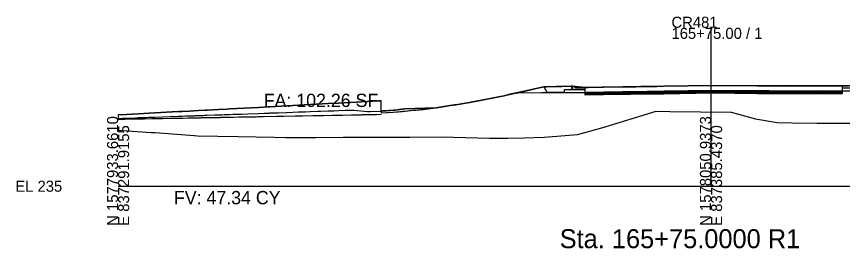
# Model space of a CAD drawing. Extents: x -26 to 303, y -16 to 6048.
# Drawn here: x -25.7 to 183.3, y 5484.3 to 5542.8 of the extents above; entities that cross this region are included whole.
import ezdxf

# ---------------------------------------------------------------- set-up
doc = ezdxf.new("R2010")
doc.units = 0
for name, color, linetype in [('ASPHALT_19MM1', 7, 'Continuous'), ('ASPHALT_9_5MM1', 7, 'Continuous'), ('CONST_LV3', 7, 'Continuous'), ('Default', 7, 'Continuous'), ('Draft_XS_Grid', 7, 'Continuous'), ('Draft_XS_Text', 7, 'Continuous'), ('DTM_P_FINISHED_GRADE', 7, 'Continuous'), ('DTM_P_FINISHED_GRADE2', 7, 'Continuous'), ('DTM_X_GROUND', 7, 'Continuous'), ('TRANS_PAVED_SHOULDERS', 7, 'Continuous'), ('X_PROFILES_1', 7, 'Continuous'), ('XS_CELL', 7, 'Continuous'), ('XS_M_SHAPES_EARTHWORK', 7, 'Continuous'), ('XS_P_ASPHALT', 7, 'Continuous'), ('XS_P_CONCRETE', 7, 'Continuous'), ('XS_P_GROUND', 7, 'Continuous'), ('XS_P_SHOULDER', 7, 'Continuous'), ('XS_P_SUBGRADE_GRANULAR', 7, 'Continuous'), ('XS_P_SUBGRADE_GRANULAR_B', 7, 'Continuous'), ('XS_SHEET_EW_TX_AREA', 7, 'Continuous'), ('XS_SHEET_EW_TX_VOLUME', 7, 'Continuous')]:
    doc.layers.add(name, color=color, linetype=linetype)

msp = doc.modelspace()

# ---------------------------------------------------------------- linework, layer by layer
at = {"layer": 'ASPHALT_19MM1'}
msp.add_lwpolyline([(118.12, 5523.35), (118.12, 5523.08), (127.61, 5523.2), (129.55, 5523.24), (138.17, 5523.35), (150, 5523.55), (161.79, 5523.45), (164.74, 5523.45), (167.03, 5523.43), (178.55, 5523.45), (180.57, 5523.44), (183.26, 5523.45), (183.26, 5523.72), (180.57, 5523.71), (178.55, 5523.72), (167.03, 5523.7), (164.74, 5523.72), (161.79, 5523.72), (150, 5523.82), (138.17, 5523.62), (129.55, 5523.51), (127.61, 5523.48), (118.12, 5523.35)], dxfattribs=at)
at = {"layer": 'ASPHALT_9_5MM1'}
msp.add_lwpolyline([(118.12, 5523.68), (118.12, 5523.56), (127.61, 5523.68), (129.55, 5523.72), (138.17, 5523.83), (150, 5524.03), (161.79, 5523.93), (164.74, 5523.93), (167.03, 5523.91), (178.55, 5523.93), (180.57, 5523.92), (183.26, 5523.93), (183.26, 5524.06), (180.57, 5524.04), (178.55, 5524.05), (167.03, 5524.04), (164.74, 5524.05), (161.79, 5524.05), (150, 5524.15), (138.17, 5523.96), (129.55, 5523.84), (127.61, 5523.81), (118.12, 5523.68)], dxfattribs=at)
at = {"layer": 'CONST_LV3'}
for points in [[(66.56, 5518.56), (68, 5518.63), (69.49, 5518.72), (70.4, 5518.78), (71.38, 5518.86), (71.92, 5518.9), (72.51, 5518.95), (73.97, 5519.08), (75.68, 5519.25), (77.14, 5519.41), (79.02, 5519.64), (80.47, 5519.83), (82.6, 5520.13), (84.03, 5520.34), (86.47, 5520.73), (87.85, 5520.96), (90.73, 5521.48), (92.01, 5521.71), (95.49, 5522.4), (96.57, 5522.62), (100.89, 5523.54), (101.62, 5523.7), (107.14, 5524.98), (107.22, 5525), (107.72, 5525.12), (110.94, 5525.19), (114.56, 5525.26), (114.68, 5525.27), (114.79, 5525.27)], [(66.56, 5518.56), (68.2, 5518.65), (69.48, 5518.73), (69.49, 5518.73), (69.49, 5518.73), (69.51, 5518.73), (69.52, 5518.73), (69.53, 5518.73), (69.54, 5518.73), (69.59, 5518.73), (69.62, 5518.73), (70.4, 5518.8), (71.35, 5518.87), (71.37, 5518.87), (71.38, 5518.87), (71.92, 5518.91), (72.51, 5518.96), (72.51, 5518.96), (72.51, 5518.96), (72.54, 5518.96), (72.57, 5518.97), (72.6, 5518.97), (72.63, 5518.97), (73.23, 5519.02), (73.83, 5519.08), (74.72, 5519.17), (75.67, 5519.27), (75.67, 5519.27), (75.68, 5519.27), (75.72, 5519.27), (75.77, 5519.28), (75.81, 5519.28), (75.86, 5519.29), (76.48, 5519.36), (77.19, 5519.44), (77.99, 5519.53), (79.01, 5519.66), (79.01, 5519.66), (79.02, 5519.66), (79.03, 5519.67), (79.03, 5519.67), (79.08, 5519.67), (79.15, 5519.68), (79.21, 5519.69), (79.28, 5519.7), (79.88, 5519.77), (80.73, 5519.89), (81.46, 5519.99), (82.6, 5520.16), (82.6, 5520.16), (82.61, 5520.16), (82.67, 5520.17), (82.77, 5520.18), (82.84, 5520.19), (82.95, 5520.21), (83.52, 5520.29), (84.51, 5520.45), (85.18, 5520.55), (86.47, 5520.77), (86.48, 5520.77), (86.5, 5520.77), (86.56, 5520.78), (86.7, 5520.8), (86.78, 5520.82), (86.93, 5520.84), (87.45, 5520.93), (88.64, 5521.14), (89.22, 5521.24), (90.73, 5521.52), (90.81, 5521.53), (91.03, 5521.57), (91.1, 5521.59), (91.33, 5521.63), (91.77, 5521.71), (93.21, 5521.99), (93.67, 5522.08), (95.45, 5522.44), (95.45, 5522.44), (95.49, 5522.45), (95.49, 5522.45), (95.52, 5522.46), (95.59, 5522.47), (95.87, 5522.52), (95.94, 5522.54), (96.25, 5522.6), (96.59, 5522.67), (98.37, 5523.05), (98.69, 5523.11), (100.89, 5523.6), (100.89, 5523.6), (100.93, 5523.61), (100.98, 5523.62), (101.38, 5523.71), (101.43, 5523.72), (101.88, 5523.82), (102.06, 5523.86), (104.28, 5524.37), (104.41, 5524.4), (107.14, 5525.05), (107.15, 5525.05), (107.46, 5525.12), (107.76, 5525.12), (107.79, 5525.12), (108.35, 5525.13), (108.43, 5525.14), (110.15, 5525.17), (111.23, 5525.19), (112.28, 5525.21), (114.47, 5525.26), (114.48, 5525.26), (114.55, 5525.27), (114.56, 5525.27), (114.63, 5525.27), (114.65, 5525.27), (114.8, 5525.27)], [(107.46, 5525.12), (107.79, 5525.12), (108.43, 5525.14), (111.23, 5525.19), (114.47, 5525.26), (114.55, 5525.27), (114.63, 5525.27), (114.8, 5525.27)], [(114.8, 5525.27), (114.8, 5524.44), (115.41, 5524.44), (116.26, 5524.44), (118.17, 5524.45), (118.17, 5524.95), (116.26, 5524.94), (115.73, 5524.94), (115.73, 5525.02), (115.41, 5525.11), (114.8, 5525.27)], [(118.12, 5524.96), (118.12, 5523.68), (127.61, 5523.81), (129.55, 5523.84), (138.17, 5523.96), (150, 5524.15), (161.79, 5524.05), (164.74, 5524.05), (167.03, 5524.04), (178.55, 5524.05), (180.57, 5524.04), (183.26, 5524.06), (183.26, 5525.33), (180.57, 5525.31), (178.55, 5525.32), (167.03, 5525.31), (164.74, 5525.32), (161.79, 5525.32), (150, 5525.43), (138.17, 5525.23), (129.55, 5525.11), (127.61, 5525.08), (118.12, 5524.96)], [(183.22, 5525.33), (183.22, 5524.83), (183.64, 5524.83), (186.77, 5524.85), (186.77, 5525.68), (185.8, 5525.43), (185.79, 5525.34), (183.64, 5525.33), (183.22, 5525.33)], [(112.9, 5523.65), (112.9, 5524.42), (114.56, 5524.43), (114.79, 5524.44)]]:
    msp.add_lwpolyline(points, dxfattribs=at)
at = {"layer": 'Default'}
msp.add_lwpolyline([(118.17, 5524.95), (118.91, 5524.96), (121.04, 5524.99), (126.79, 5525.07), (129.55, 5525.11), (129.69, 5525.11), (131, 5525.13), (132.25, 5525.15), (135.58, 5525.19), (138.17, 5525.23), (150, 5525.43), (161.85, 5525.32), (164.64, 5525.32), (164.71, 5525.32), (164.73, 5525.32), (164.74, 5525.32), (165.15, 5525.32), (165.21, 5525.32), (168.55, 5525.3), (178.8, 5525.32), (182.04, 5525.31), (182.08, 5525.31), (182.1, 5525.31), (182.1, 5525.31), (182.38, 5525.31), (183.22, 5525.33)], dxfattribs=at)
msp.add_lwpolyline([(118.17, 5523.08), (118.17, 5524.95), (118.91, 5524.96), (121.04, 5524.99), (126.79, 5525.07), (129.55, 5525.11), (129.69, 5525.11), (131, 5525.13), (132.25, 5525.15), (135.58, 5525.19), (138.17, 5525.23), (150, 5525.43), (161.85, 5525.32), (164.64, 5525.32), (164.71, 5525.32), (164.73, 5525.32), (164.74, 5525.32), (165.15, 5525.32), (165.21, 5525.32), (168.55, 5525.3), (178.8, 5525.32), (182.04, 5525.31), (182.08, 5525.31), (182.1, 5525.31), (182.1, 5525.31), (182.38, 5525.31), (183.22, 5525.33), (183.22, 5523.45), (180.57, 5523.44), (178.55, 5523.45), (167.03, 5523.43), (164.74, 5523.45), (161.79, 5523.45), (150, 5523.55), (138.17, 5523.35), (129.55, 5523.24), (127.61, 5523.2)], close=True, dxfattribs=at)
at = {"layer": 'DTM_P_FINISHED_GRADE'}
msp.add_lwpolyline([(118.12, 5524.96), (127.61, 5525.08), (129.55, 5525.11), (138.17, 5525.23), (150, 5525.43), (161.79, 5525.32), (164.74, 5525.32), (167.03, 5525.31), (178.55, 5525.32), (180.57, 5525.31), (183.26, 5525.33)], dxfattribs=at)
at = {"layer": 'DTM_P_FINISHED_GRADE2'}
msp.add_lwpolyline([(66.56, 5518.56), (68, 5518.63), (69.49, 5518.72), (70.4, 5518.78), (70.94, 5518.82), (71.92, 5518.9), (73.37, 5519.03), (73.97, 5519.08), (75.43, 5519.24), (77.14, 5519.41), (78.6, 5519.6), (80.47, 5519.83), (81.93, 5520.04), (84.03, 5520.34), (85.47, 5520.58), (87.85, 5520.96), (89.24, 5521.22), (92.01, 5521.71), (93.29, 5521.97), (94.58, 5522.25), (97.65, 5522.85), (98.77, 5523.12), (102.35, 5523.88), (103.13, 5524.07), (107.3, 5525.02), (107.72, 5525.12), (110.94, 5525.19), (114.56, 5525.26), (114.68, 5525.27), (114.79, 5525.27), (115.59, 5525.05), (115.71, 5525.02), (115.71, 5525.01), (115.71, 5524.94), (117.31, 5524.95), (118.12, 5524.96), (127.61, 5525.08), (129.55, 5525.11), (138.17, 5525.23), (150, 5525.43), (161.79, 5525.32), (164.74, 5525.32), (167.03, 5525.31), (178.55, 5525.32), (180.57, 5525.31), (183.26, 5525.33)], dxfattribs=at)
at = {"layer": 'DTM_X_GROUND'}
for points in [[(0, 5517.13), (1.15, 5517.17), (2.13, 5517.2), (4.44, 5517.28), (5.15, 5517.31), (6.05, 5517.34), (7.15, 5517.38), (7.81, 5517.4), (9.32, 5517.46), (13.15, 5517.59), (15.27, 5517.67), (15.43, 5517.67), (15.93, 5517.69), (16.15, 5517.7), (17.18, 5517.73), (17.24, 5517.74), (17.46, 5517.74), (17.99, 5517.76), (19.34, 5517.81), (19.6, 5517.82), (20.31, 5517.85), (21.53, 5517.89), (21.84, 5517.9), (22.41, 5517.92), (22.56, 5517.92), (24.44, 5517.99), (25.39, 5518.03), (26.26, 5518.06), (26.86, 5518.08), (27.21, 5518.09), (27.99, 5518.12), (28.18, 5518.12), (29.01, 5518.15), (31.19, 5518.23), (32.8, 5518.29), (35.51, 5518.39), (37, 5518.44), (37.94, 5518.47), (38.2, 5518.48), (38.37, 5518.49), (39.09, 5518.51), (40.62, 5518.57), (42.49, 5518.63), (42.65, 5518.64), (45.63, 5518.74), (47.33, 5518.8), (48.56, 5518.85), (50.62, 5518.92), (51.17, 5518.94), (53.16, 5519.01), (54.44, 5519.06), (54.61, 5519.06), (55.75, 5519.1), (57.41, 5519.16), (58.75, 5519.21), (59.61, 5519.24), (63.13, 5518.84), (63.81, 5518.87), (66.25, 5518.96), (66.78, 5518.99), (67, 5519), (67.07, 5519.01), (67.45, 5519.03), (67.68, 5519.04), (67.75, 5519.04), (68.5, 5519.09), (68.93, 5519.13), (69.78, 5519.21), (70.11, 5519.24), (71.21, 5519.38), (71.28, 5519.38), (72.43, 5519.55), (80.47, 5519.83), (81.93, 5520.04), (84.03, 5520.34), (85.13, 5520.52), (85.47, 5520.58), (87.85, 5520.96), (89, 5521.17), (89.24, 5521.22), (92.01, 5521.71), (93.29, 5521.97), (94.18, 5522.17), (94.58, 5522.25), (97.65, 5522.85), (98.77, 5523.12), (102.35, 5523.88), (102.45, 5523.9), (103.13, 5524.07), (103.13, 5524.07), (107.3, 5525.02), (107.72, 5525.12), (110.94, 5525.19), (114.56, 5525.26), (114.68, 5525.27), (114.79, 5525.27), (114.95, 5525.25), (118.12, 5524.96), (127.61, 5525.08), (129.55, 5525.11), (138.17, 5525.23), (150, 5525.43), (161.79, 5525.32), (164.74, 5525.32), (167.03, 5525.31), (178.55, 5525.32), (180.57, 5525.31), (183.26, 5525.33), (184.75, 5525.38)], [(0, 5514.15), (8.39, 5513.55), (9.36, 5513.53), (19.24, 5512.79), (19.31, 5512.79), (20.08, 5512.73), (30.35, 5512.53), (39.51, 5512.35), (42.48, 5512.29), (50.02, 5512.34), (56.93, 5512.37), (65.45, 5512.36), (73.85, 5512.39), (81.83, 5512.43), (93.98, 5512.09), (98.6, 5512.09), (102.8, 5512.24), (107.81, 5512.42), (115.22, 5512.99), (116.25, 5513.02), (122.34, 5514.73), (136.13, 5518.91), (139.56, 5518.89), (155.1, 5518.72), (161.24, 5517), (166.75, 5516.08), (170.55, 5516.03), (176.89, 5515.95), (180.55, 5515.96), (186.64, 5515.89)]]:
    msp.add_lwpolyline(points, dxfattribs=at)
at = {"layer": 'TRANS_PAVED_SHOULDERS'}
msp.add_lwpolyline([(118.12, 5523.56), (118.12, 5523.35), (127.61, 5523.48), (129.55, 5523.51), (138.17, 5523.62), (150, 5523.82), (161.79, 5523.72), (164.74, 5523.72), (167.03, 5523.7), (178.55, 5523.72), (180.57, 5523.71), (183.26, 5523.72), (183.26, 5523.93), (180.57, 5523.92), (178.55, 5523.93), (167.03, 5523.91), (164.74, 5523.93), (161.79, 5523.93), (150, 5524.03), (138.17, 5523.83), (129.55, 5523.72), (127.61, 5523.68), (118.12, 5523.56)], dxfattribs=at)
at = {"layer": 'XS_CELL'}
for p, q in [((150, 5500), (150, 5540)), ((0, 5500), (150, 5500)), ((150, 5500), (300, 5500))]:
    msp.add_line(p, q, dxfattribs=at)
at = {"layer": 'XS_M_SHAPES_EARTHWORK'}
for points in [[(126.82, 5525.07), (118.12, 5524.96), (114.95, 5525.25), (114.79, 5525.27), (114.68, 5525.27), (114.56, 5525.26), (110.94, 5525.19), (107.72, 5525.12), (107.3, 5525.02), (103.13, 5524.07), (102.45, 5523.9), (102.35, 5523.88), (98.77, 5523.12), (97.65, 5522.85), (94.58, 5522.25), (94.18, 5522.17), (93.29, 5521.97), (92.01, 5521.71), (95.49, 5522.4), (96.57, 5522.62), (100.89, 5523.54), (101.18, 5523.61), (107.14, 5523.63), (108.45, 5523.63), (112.9, 5523.65), (114.56, 5523.66), (114.79, 5523.66), (118.12, 5523.68), (118.12, 5523.56), (118.12, 5523.35), (118.12, 5523.08), (118.17, 5523.08), (118.17, 5524.95), (118.91, 5524.96), (121.04, 5524.99), (126.79, 5525.07)], [(132.25, 5525.15), (130.81, 5525.13), (131, 5525.13)], [(136.32, 5525.2), (132.25, 5525.15), (135.58, 5525.19)], [(179.9, 5525.32), (178.55, 5525.32), (167.49, 5525.31), (168.55, 5525.3), (178.8, 5525.32)], [(0, 5518.03), (0, 5517.13), (1.15, 5517.17), (2.13, 5517.2), (4.44, 5517.28), (5.15, 5517.31), (6.05, 5517.34), (7.15, 5517.38), (7.81, 5517.4), (9.32, 5517.46), (13.15, 5517.59), (15.27, 5517.67), (15.43, 5517.67), (15.93, 5517.69), (16.15, 5517.7), (17.18, 5517.73), (17.24, 5517.74), (17.46, 5517.74), (17.99, 5517.76), (19.34, 5517.81), (19.6, 5517.82), (20.31, 5517.85), (21.53, 5517.89), (21.84, 5517.9), (22.41, 5517.92), (22.56, 5517.92), (24.44, 5517.99), (25.39, 5518.03), (26.26, 5518.06), (26.86, 5518.08), (27.21, 5518.09), (27.99, 5518.12), (28.18, 5518.12), (29.01, 5518.15), (31.19, 5518.23), (32.8, 5518.29), (35.51, 5518.39), (37, 5518.44), (37.94, 5518.47), (38.2, 5518.48), (38.37, 5518.49), (39.09, 5518.51), (40.62, 5518.57), (42.49, 5518.63), (42.65, 5518.64), (45.63, 5518.74), (47.33, 5518.8), (48.56, 5518.85), (50.62, 5518.92), (51.17, 5518.94), (53.16, 5519.01), (54.44, 5519.06), (54.61, 5519.06), (55.75, 5519.1), (57.41, 5519.16), (58.75, 5519.21), (59.61, 5519.24), (63.13, 5518.84), (63.81, 5518.87), (66.25, 5518.96), (66.56, 5518.98), (66.56, 5521.58), (66.4, 5521.58), (65.88, 5521.55), (60.31, 5521.25), (58.75, 5521.16), (55.75, 5521), (53.16, 5520.86), (48.56, 5520.61), (45.63, 5520.45), (38.37, 5520.06), (37.94, 5520.04), (35.51, 5519.91), (28.18, 5519.52), (27.63, 5519.49), (25.39, 5519.37), (22.56, 5519.22), (22.1, 5519.2), (20.31, 5519.1), (17.99, 5518.98), (16.21, 5518.88), (15.49, 5518.84), (15.27, 5518.83), (7.81, 5518.44), (5.15, 5518.3), (2.13, 5518.14)], [(86.47, 5520.73), (87.85, 5520.96), (85.47, 5520.58), (85.13, 5520.52), (84.03, 5520.34)], [(90.73, 5521.48), (92.01, 5521.71), (89.24, 5521.22), (89, 5521.17), (87.85, 5520.96)], [(68, 5518.63), (69.49, 5518.72), (70.4, 5518.78), (71.38, 5518.86), (71.92, 5518.9), (72.51, 5518.95), (73.97, 5519.08), (75.68, 5519.25), (77.14, 5519.41), (79.02, 5519.64), (80.47, 5519.83), (72.43, 5519.55), (71.28, 5519.38), (71.21, 5519.38), (70.11, 5519.24), (69.78, 5519.21), (68.93, 5519.13), (68.5, 5519.09), (67.75, 5519.04), (67.68, 5519.04), (67.45, 5519.03), (67.07, 5519.01), (67, 5519), (66.78, 5518.99), (66.56, 5518.98), (66.56, 5518.56)], [(82.6, 5520.13), (84.03, 5520.34), (81.93, 5520.04), (80.47, 5519.83)]]:
    msp.add_lwpolyline(points, close=True, dxfattribs=at)
msp.add_lwpolyline([(184.75, 5525.38), (183.26, 5525.33), (180.68, 5525.31), (182.04, 5525.31), (182.08, 5525.31), (182.1, 5525.31), (182.1, 5525.31), (182.38, 5525.31), (183.22, 5525.33), (183.22, 5523.45), (183.26, 5523.45), (183.26, 5523.72), (183.26, 5523.93), (183.26, 5524.06), (186.8, 5524.08)], dxfattribs=at)
at = {"layer": 'XS_P_ASPHALT'}
msp.add_lwpolyline([(118.12, 5524.96), (127.61, 5525.08), (129.55, 5525.11), (138.17, 5525.23), (150, 5525.43), (161.79, 5525.32), (164.74, 5525.32), (167.03, 5525.31), (178.55, 5525.32), (180.57, 5525.31), (183.26, 5525.33)], dxfattribs=at)
at = {"layer": 'XS_P_CONCRETE'}
msp.add_lwpolyline([(118.12, 5524.96), (118.12, 5524.46), (114.79, 5524.44), (114.79, 5525.27), (115.71, 5525.02), (115.71, 5524.94), (118.12, 5524.96)], dxfattribs=at)
at = {"layer": 'XS_P_GROUND'}
for points in [[(66.56, 5518.56), (68, 5518.63), (69.49, 5518.72), (70.4, 5518.78), (71.38, 5518.86), (71.92, 5518.9), (72.51, 5518.95), (73.97, 5519.08), (75.68, 5519.25), (77.14, 5519.41), (79.02, 5519.64), (80.47, 5519.83), (82.6, 5520.13), (84.03, 5520.34), (86.47, 5520.73), (87.85, 5520.96), (90.73, 5521.48), (92.01, 5521.71), (95.49, 5522.4), (96.57, 5522.62), (100.89, 5523.54), (101.62, 5523.7), (107.14, 5524.98), (107.22, 5525), (107.72, 5525.12)], [(66.56, 5518.56), (68.2, 5518.65), (69.48, 5518.73), (69.49, 5518.73), (69.49, 5518.73), (69.51, 5518.73), (69.52, 5518.73), (69.53, 5518.73), (69.54, 5518.73), (69.59, 5518.73), (69.62, 5518.73), (70.4, 5518.8), (71.35, 5518.87), (71.37, 5518.87), (71.38, 5518.87), (71.92, 5518.91), (72.51, 5518.96), (72.51, 5518.96), (72.51, 5518.96), (72.54, 5518.96), (72.57, 5518.97), (72.6, 5518.97), (72.63, 5518.97), (73.23, 5519.02), (73.83, 5519.08), (74.72, 5519.17), (75.67, 5519.27), (75.67, 5519.27), (75.68, 5519.27), (75.72, 5519.27), (75.77, 5519.28), (75.81, 5519.28), (75.86, 5519.29), (76.48, 5519.36), (77.19, 5519.44), (77.99, 5519.53), (79.01, 5519.66), (79.01, 5519.66), (79.02, 5519.66), (79.03, 5519.67), (79.03, 5519.67), (79.08, 5519.67), (79.15, 5519.68), (79.21, 5519.69), (79.28, 5519.7), (79.88, 5519.77), (80.73, 5519.89), (81.46, 5519.99), (82.6, 5520.16), (82.6, 5520.16), (82.61, 5520.16), (82.67, 5520.17), (82.77, 5520.18), (82.84, 5520.19), (82.95, 5520.21), (83.52, 5520.29), (84.51, 5520.45), (85.18, 5520.55), (86.47, 5520.77), (86.48, 5520.77), (86.5, 5520.77), (86.56, 5520.78), (86.7, 5520.8), (86.78, 5520.82), (86.93, 5520.84), (87.45, 5520.93), (88.64, 5521.14), (89.22, 5521.24), (90.73, 5521.52), (90.81, 5521.53), (91.03, 5521.57), (91.1, 5521.59), (91.33, 5521.63), (91.77, 5521.71), (93.21, 5521.99), (93.67, 5522.08), (95.45, 5522.44), (95.45, 5522.44), (95.49, 5522.45), (95.49, 5522.45), (95.52, 5522.46), (95.59, 5522.47), (95.87, 5522.52), (95.94, 5522.54), (96.25, 5522.6), (96.59, 5522.67), (98.37, 5523.05), (98.69, 5523.11), (100.89, 5523.6), (100.89, 5523.6), (100.93, 5523.61), (100.98, 5523.62), (101.38, 5523.71), (101.43, 5523.72), (101.88, 5523.82), (102.06, 5523.86), (104.28, 5524.37), (104.41, 5524.4), (107.14, 5525.05), (107.15, 5525.05), (107.46, 5525.12)], [(0, 5518.03), (2.13, 5518.14), (5.15, 5518.3), (7.81, 5518.44), (15.27, 5518.83), (15.49, 5518.84), (16.21, 5518.88), (17.99, 5518.98), (20.31, 5519.1), (22.1, 5519.2), (22.56, 5519.22), (25.39, 5519.37), (27.63, 5519.49), (28.18, 5519.52), (35.51, 5519.91), (37.94, 5520.04), (38.37, 5520.06), (45.63, 5520.45), (48.56, 5520.61), (53.16, 5520.86), (55.75, 5521), (58.75, 5521.16), (60.31, 5521.25), (65.88, 5521.55), (66.4, 5521.58), (66.56, 5521.58)], [(0, 5516.92), (1.27, 5516.94), (1.4, 5516.95), (1.71, 5516.95), (3.24, 5516.98), (6.31, 5517.03), (6.38, 5517.04), (6.51, 5517.04), (6.7, 5517.04), (8.53, 5517.07), (11.32, 5517.13), (11.33, 5517.13), (11.36, 5517.13), (13.37, 5517.16), (16.12, 5517.21), (16.23, 5517.21), (16.4, 5517.22), (17.74, 5517.24), (19.36, 5517.27), (20.09, 5517.29), (20.92, 5517.3), (21.17, 5517.31), (21.45, 5517.31), (23.81, 5517.35), (25.72, 5517.39), (25.9, 5517.39), (26.06, 5517.4), (26.3, 5517.4), (26.49, 5517.4), (29.2, 5517.45), (30.52, 5517.48), (31.23, 5517.49), (31.53, 5517.5), (34.92, 5517.56), (35.32, 5517.57), (36.56, 5517.59), (36.58, 5517.59), (36.74, 5517.6), (40.11, 5517.66), (40.18, 5517.66), (41.62, 5517.69), (41.83, 5517.69), (44.91, 5517.75), (45.1, 5517.76), (46.66, 5517.79), (49.35, 5517.84), (49.71, 5517.84), (51.48, 5517.88), (51.7, 5517.88), (51.91, 5517.88), (51.94, 5517.88), (54.23, 5517.93), (54.51, 5517.93), (56.51, 5517.97), (56.75, 5517.97), (59.05, 5518.01), (59.31, 5518.02), (61.55, 5518.06), (61.79, 5518.07), (63.9, 5518.11), (64.11, 5518.12), (65.36, 5518.14), (66.56, 5518.16)]]:
    msp.add_lwpolyline(points, dxfattribs=at)
at = {"layer": 'XS_P_SHOULDER'}
msp.add_lwpolyline([(107.72, 5525.12), (114.56, 5525.26), (114.79, 5525.27)], dxfattribs=at)
at = {"layer": 'XS_P_SUBGRADE_GRANULAR'}
for points in [[(112.9, 5523.65), (114.56, 5523.66), (114.79, 5523.66)], [(114.79, 5523.66), (118.12, 5523.68)], [(118.12, 5523.68), (127.61, 5523.81), (129.55, 5523.84), (138.17, 5523.96), (150, 5524.15), (161.79, 5524.05), (164.74, 5524.05), (167.03, 5524.04), (178.55, 5524.05), (180.57, 5524.04), (183.26, 5524.06)]]:
    msp.add_lwpolyline(points, dxfattribs=at)
at = {"layer": 'XS_P_SUBGRADE_GRANULAR_B'}
for points in [[(107.72, 5525.12), (108.35, 5523.9), (108.45, 5523.63)], [(101.17, 5523.61), (107.14, 5523.63), (108.45, 5523.63)], [(112.9, 5523.65), (108.45, 5523.63)]]:
    msp.add_lwpolyline(points, dxfattribs=at)

# ---------------------------------------------------------------- texts
at = {"layer": 'Draft_XS_Grid'}
msp.add_text('-', height=0.0001, dxfattribs=at).set_placement((0, 5500))
at = {"layer": 'Draft_XS_Text'}
msp.add_text('Sta. 165+75.0000 R1', height=4.8, dxfattribs=at).set_placement((111.72, 5484.35))
at = {"layer": 'X_PROFILES_1'}
msp.add_text('X', height=0.24, dxfattribs=at).set_placement((107.38, 5525))
at = {"layer": 'XS_CELL'}
for s, p in [('CR481', (140, 5540)), ('165+75.00 / 1', (140, 5537.2)), ('EL 235', (-26, 5498.6))]:
    msp.add_text(s, height=2.8, dxfattribs=at).set_placement(p)
for s, p in [('N 1577933.6610', (0, 5490)), ('N 1578050.9373', (150, 5490)), ('E 837291.9155', (2.8, 5490)), ('E 837385.4370', (152.8, 5490))]:
    msp.add_text(s, height=2.8, rotation=90, dxfattribs=at).set_placement(p)
at = {"layer": 'XS_P_GROUND'}
for p in [(107.64, 5525), (114.72, 5525.15)]:
    msp.add_text('X', height=0.24, dxfattribs=at).set_placement(p)
at = {"layer": 'XS_SHEET_EW_TX_AREA'}
msp.add_text('FA: 102.26 SF', height=3.36, dxfattribs=at).set_placement((36.85, 5520))
at = {"layer": 'XS_SHEET_EW_TX_VOLUME'}
msp.add_text('FV: 47.34 CY', height=3.36, dxfattribs=at).set_placement((14.13, 5495.44))

doc.saveas('drawing.dxf')
